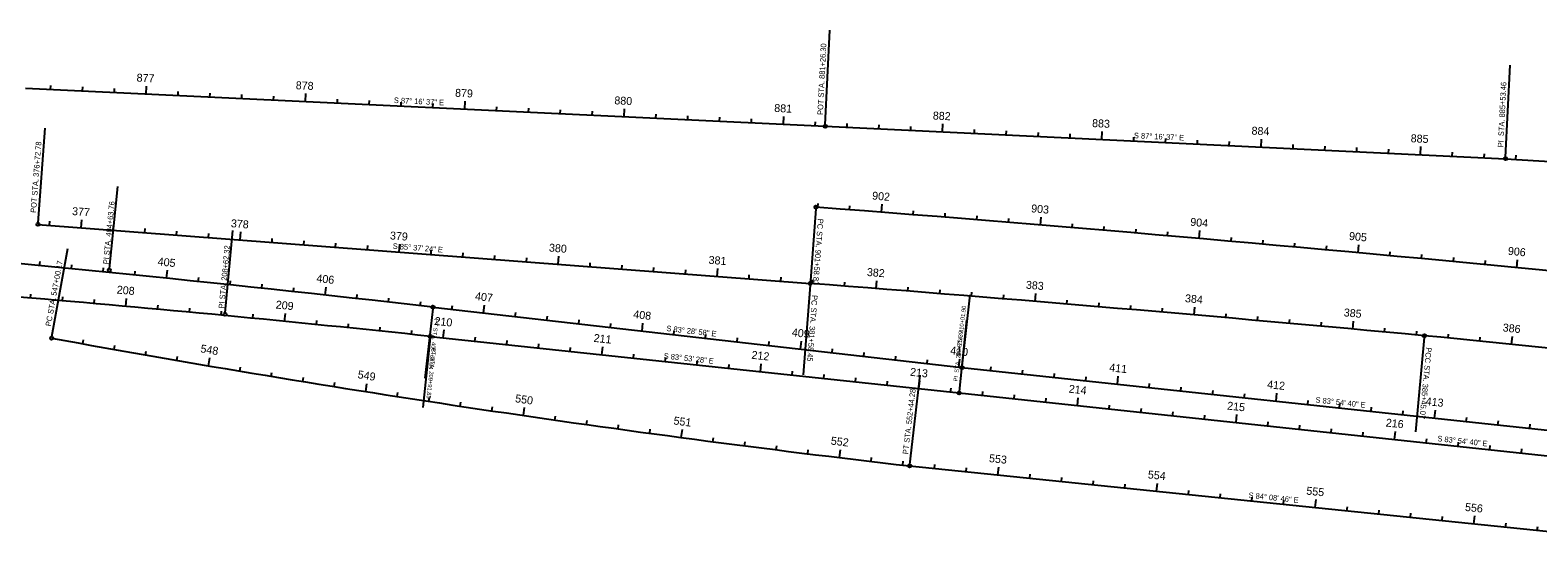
# Model space of a CAD drawing. Extents: x 919452 to 931278, y 583254 to 665650.
# Drawn here: x 926069 to 927014, y 636633 to 636954 of the extents above; entities that cross this region are included whole.
import ezdxf

# ---------------------------------------------------------------- set-up
doc = ezdxf.new("R2010")
doc.units = 0
for name, color, linetype in [('CLConst_dp', 7, 'Continuous'), ('CurveDataLabel_dp', 7, 'Continuous'), ('StationTicL_dp', 7, 'Continuous'), ('StationTicS_dp', 7, 'Continuous'), ('TextBLStation', 7, 'Continuous'), ('TextLabel', 7, 'Continuous')]:
    doc.layers.add(name, color=color, linetype=linetype)

msp = doc.modelspace()

# ---------------------------------------------------------------- linework, layer by layer
at = {"layer": 'CLConst_dp'}
for p, q in [((926065.6, 636917.34), (926567.14, 636893.49)), ((926567.14, 636893.49), (926993.81, 636873.2)), ((926993.81, 636873.2), (927628.09, 636834.88)), ((926073.42, 636831.99), (926557.68, 636794.93)), ((926321.15, 636780.1), (926652.85, 636742.2)), ((926319.5, 636761.79), (926651.16, 636726.29)), ((926652.85, 636742.2), (927135.36, 636690.73)), ((926651.16, 636726.29), (927289.95, 636658.15)), ((926620.06, 636680.55), (927084.21, 636632.96))]:
    msp.add_line(p, q, dxfattribs=at)
for centre, radius, start, end in [((924808.61, 613941.45), 22968.31, 83.189634, 85.623449), ((924651.1, 622161.18), 14714, 83.482815, 85.073773), ((924808.61, 613941.45), 22920.31, 84.656985, 85.623449), ((925098.46, 625352.94), 11474, 83.891103, 85.184769), ((926386.43, 630812.14), 5976, 78.354474, 84.656985), ((927580.46, 644977.15), 8352, 259.664221, 263.396902)]:
    msp.add_arc(centre, radius, start, end, dxfattribs=at)
at = {"layer": 'CurveDataLabel_dp'}
for p, q in [((926567.19, 636894.49), (926570.01, 636953.77)), ((926993.86, 636874.19), (926996.6, 636931.84)), ((926073.5, 636832.98), (926078.03, 636892.23)), ((926118.27, 636804.28), (926123.43, 636855.78)), ((926561.27, 636841.79), (926556.97, 636785.6)), ((926190.8, 636776.57), (926195.73, 636828.16)), ((926082.15, 636761.66), (926092.24, 636816.93)), ((926557.6, 636793.93), (926553.31, 636737.77)), ((926652.97, 636743.2), (926658.08, 636787.93)), ((926321.04, 636779.1), (926316.06, 636735.55)), ((926651.26, 636727.29), (926656.05, 636772.06)), ((926319.4, 636760.79), (926314.72, 636717.12)), ((926942.81, 636761.18), (926937.27, 636701.97)), ((926620.17, 636681.54), (926626.64, 636737.4))]:
    msp.add_line(p, q, dxfattribs=at)
for centre in [(926567.14, 636893.49), (926993.81, 636873.2), (926561.34, 636842.79), (926073.42, 636831.99), (926118.17, 636803.28), (926557.68, 636794.93), (926321.15, 636780.1), (926190.7, 636775.57), (926081.97, 636760.67), (926319.5, 636761.79), (926942.91, 636762.17), (926652.85, 636742.2), (926651.16, 636726.29), (926620.06, 636680.55)]:
    msp.add_circle(centre, 1, dxfattribs=at)
at = {"layer": 'StationTicL_dp'}
for p, q in [((926141.32, 636913.74), (926141.56, 636918.74)), ((926241.2, 636908.99), (926241.44, 636913.98)), ((926341.09, 636904.24), (926341.33, 636909.23)), ((926440.98, 636899.49), (926441.22, 636904.48)), ((926540.87, 636894.74), (926541.1, 636899.73)), ((926640.75, 636889.99), (926640.99, 636894.98)), ((926740.64, 636885.24), (926740.88, 636890.23)), ((926840.53, 636880.49), (926840.76, 636885.48)), ((926940.41, 636875.73), (926940.65, 636880.73)), ((926602.39, 636839.61), (926602.78, 636844.59)), ((926702.07, 636831.58), (926702.48, 636836.56)), ((926100.56, 636829.91), (926100.95, 636834.9)), ((926200.27, 636822.28), (926200.65, 636827.26)), ((926801.71, 636823.12), (926802.14, 636828.1)), ((926299.98, 636814.65), (926300.36, 636819.63)), ((926901.31, 636814.22), (926901.77, 636819.2)), ((926399.69, 636807.02), (926400.07, 636812)), ((927000.88, 636804.9), (927001.35, 636809.87)), ((926154.1, 636798.21), (926154.61, 636803.19)), ((926499.4, 636799.39), (926499.78, 636804.37)), ((926253.54, 636787.66), (926254.08, 636792.63)), ((926599.1, 636791.72), (926599.49, 636796.7)), ((926128.58, 636780.61), (926129.03, 636785.59)), ((926352.91, 636776.47), (926353.48, 636781.44)), ((926698.78, 636783.69), (926699.19, 636788.67)), ((926798.42, 636775.22), (926798.86, 636780.2)), ((926228.14, 636771.2), (926228.63, 636776.17)), ((926898.03, 636766.33), (926898.48, 636771.3)), ((926327.61, 636760.92), (926328.14, 636765.89)), ((926452.26, 636765.12), (926452.83, 636770.09)), ((926997.57, 636756.81), (926998.08, 636761.78)), ((926427.04, 636750.28), (926427.57, 636755.25)), ((926551.62, 636753.77), (926552.19, 636758.74)), ((926180.29, 636743.35), (926181.13, 636748.28)), ((926526.47, 636739.64), (926527.01, 636744.61)), ((926650.97, 636742.42), (926651.54, 636747.39)), ((926625.91, 636729), (926626.44, 636733.97)), ((926750.41, 636731.8), (926750.94, 636736.77)), ((926278.97, 636727.18), (926279.75, 636732.11)), ((926725.34, 636718.38), (926725.87, 636723.35)), ((926849.84, 636721.19), (926850.37, 636726.16)), ((926377.84, 636712.18), (926378.56, 636717.13)), ((926949.28, 636710.58), (926949.81, 636715.55)), ((926824.78, 636707.77), (926825.31, 636712.74)), ((926476.88, 636698.38), (926477.54, 636703.33)), ((926924.21, 636697.17), (926924.74, 636702.14)), ((926576.08, 636685.76), (926576.68, 636690.72)), ((926675.49, 636674.87), (926676, 636679.84)), ((926774.96, 636664.67), (926775.47, 636669.64)), ((926874.44, 636654.47), (926874.95, 636659.44)), ((926973.92, 636644.27), (926974.43, 636649.24))]:
    msp.add_line(p, q, dxfattribs=at)
at = {"layer": 'StationTicS_dp'}
for p, q in [((926081.39, 636916.59), (926081.5, 636919.09)), ((926101.36, 636915.64), (926101.48, 636918.14)), ((926121.34, 636914.69), (926121.46, 636917.19)), ((926161.29, 636912.79), (926161.41, 636915.29)), ((926181.27, 636911.84), (926181.39, 636914.34)), ((926201.25, 636910.89), (926201.37, 636913.39)), ((926221.23, 636909.94), (926221.35, 636912.44)), ((926261.18, 636908.04), (926261.3, 636910.54)), ((926281.16, 636907.09), (926281.28, 636909.59)), ((926301.14, 636906.14), (926301.26, 636908.64)), ((926321.11, 636905.19), (926321.23, 636907.69)), ((926361.07, 636903.29), (926361.19, 636905.79)), ((926381.05, 636902.34), (926381.17, 636904.84)), ((926401.02, 636901.39), (926401.14, 636903.89)), ((926421, 636900.44), (926421.12, 636902.94)), ((926460.96, 636898.54), (926461.07, 636901.04)), ((926480.93, 636897.59), (926481.05, 636900.09)), ((926500.91, 636896.64), (926501.03, 636899.14)), ((926520.89, 636895.69), (926521.01, 636898.19)), ((926560.84, 636893.79), (926560.96, 636896.29)), ((926580.82, 636892.84), (926580.94, 636895.33)), ((926600.8, 636891.89), (926600.92, 636894.38)), ((926620.78, 636890.94), (926620.89, 636893.43)), ((926660.73, 636889.04), (926660.85, 636891.53)), ((926680.71, 636888.09), (926680.83, 636890.58)), ((926700.69, 636887.14), (926700.8, 636889.63)), ((926720.66, 636886.19), (926720.78, 636888.68)), ((926760.62, 636884.29), (926760.74, 636886.78)), ((926780.59, 636883.34), (926780.71, 636885.83)), ((926800.57, 636882.39), (926800.69, 636884.88)), ((926820.55, 636881.44), (926820.67, 636883.93)), ((926860.5, 636879.54), (926860.62, 636882.03)), ((926880.48, 636878.59), (926880.6, 636881.08)), ((926900.46, 636877.64), (926900.58, 636880.13)), ((926920.44, 636876.69), (926920.56, 636879.18)), ((926960.39, 636874.78), (926960.51, 636877.28)), ((926980.37, 636873.83), (926980.49, 636876.33)), ((927000.34, 636872.8), (927000.49, 636875.3)), ((926562.51, 636842.7), (926562.7, 636845.19)), ((926582.45, 636841.16), (926582.64, 636843.65)), ((926622.33, 636838.04), (926622.53, 636840.53)), ((926642.27, 636836.45), (926642.46, 636838.94)), ((926662.2, 636834.84), (926662.4, 636837.33)), ((926080.62, 636831.44), (926080.81, 636833.93)), ((926120.51, 636828.38), (926120.7, 636830.88)), ((926140.45, 636826.86), (926140.64, 636829.35)), ((926160.39, 636825.33), (926160.58, 636827.82)), ((926682.13, 636833.22), (926682.34, 636835.71)), ((926722, 636829.92), (926722.21, 636832.41)), ((926741.93, 636828.25), (926742.14, 636830.74)), ((926761.86, 636826.56), (926762.07, 636829.05)), ((926781.78, 636824.85), (926782, 636827.34)), ((926180.33, 636823.81), (926180.52, 636826.3)), ((926220.21, 636820.75), (926220.41, 636823.25)), ((926240.16, 636819.23), (926240.35, 636821.72)), ((926260.1, 636817.7), (926260.29, 636820.19)), ((926280.04, 636816.17), (926280.23, 636818.67)), ((926821.63, 636821.38), (926821.85, 636823.87)), ((926841.55, 636819.61), (926841.78, 636822.1)), ((926861.48, 636817.83), (926861.7, 636820.32)), ((926881.39, 636816.04), (926881.62, 636818.53)), ((926074.49, 636806.17), (926074.74, 636808.66)), ((926319.92, 636813.12), (926320.11, 636815.61)), ((926339.86, 636811.6), (926340.06, 636814.09)), ((926359.81, 636810.07), (926360, 636812.56)), ((926379.75, 636808.54), (926379.94, 636811.04)), ((926419.63, 636805.49), (926419.82, 636807.98)), ((926921.23, 636812.39), (926921.46, 636814.88)), ((926941.14, 636810.55), (926941.37, 636813.03)), ((926961.06, 636808.68), (926961.29, 636811.17)), ((926980.97, 636806.8), (926981.2, 636809.29)), ((926094.4, 636804.22), (926094.64, 636806.71)), ((926114.3, 636802.25), (926114.55, 636804.73)), ((926134.2, 636800.24), (926134.45, 636802.73)), ((926173.99, 636796.16), (926174.25, 636798.64)), ((926439.57, 636803.96), (926439.76, 636806.46)), ((926459.52, 636802.44), (926459.71, 636804.93)), ((926479.46, 636800.91), (926479.65, 636803.4)), ((926519.34, 636797.86), (926519.53, 636800.35)), ((926539.28, 636796.33), (926539.47, 636798.83)), ((926193.88, 636794.07), (926194.14, 636796.56)), ((926213.77, 636791.96), (926214.04, 636794.45)), ((926233.66, 636789.83), (926233.92, 636792.31)), ((926559.22, 636794.81), (926559.41, 636797.3)), ((926579.16, 636793.27), (926579.36, 636795.76)), ((926619.04, 636790.15), (926619.24, 636792.64)), ((926638.98, 636788.56), (926639.18, 636791.05)), ((926658.91, 636786.95), (926659.12, 636789.44)), ((926068.81, 636785.84), (926069.02, 636788.33)), ((926088.74, 636784.13), (926088.96, 636786.62)), ((926108.66, 636782.39), (926108.88, 636784.88)), ((926148.5, 636778.8), (926148.73, 636781.29)), ((926273.42, 636785.47), (926273.69, 636787.96)), ((926293.29, 636783.25), (926293.57, 636785.74)), ((926313.17, 636781.01), (926313.45, 636783.49)), ((926333.04, 636778.74), (926333.32, 636781.22)), ((926678.85, 636785.33), (926679.05, 636787.82)), ((926718.71, 636782.03), (926718.92, 636784.52)), ((926738.64, 636780.35), (926738.85, 636782.85)), ((926758.57, 636778.66), (926758.78, 636781.15)), ((926168.42, 636776.95), (926168.65, 636779.44)), ((926188.33, 636775.07), (926188.57, 636777.55)), ((926208.24, 636773.15), (926208.48, 636775.64)), ((926248.04, 636769.21), (926248.29, 636771.7)), ((926372.78, 636774.2), (926373.06, 636776.68)), ((926392.65, 636771.93), (926392.94, 636774.41)), ((926412.52, 636769.66), (926412.81, 636772.14)), ((926778.5, 636776.95), (926778.71, 636779.44)), ((926818.35, 636773.48), (926818.56, 636775.97)), ((926838.27, 636771.72), (926838.49, 636774.21)), ((926858.19, 636769.94), (926858.41, 636772.43)), ((926878.11, 636768.14), (926878.33, 636770.63)), ((926267.94, 636767.19), (926268.19, 636769.68)), ((926287.83, 636765.13), (926288.09, 636767.62)), ((926307.72, 636763.04), (926307.99, 636765.53)), ((926347.5, 636758.79), (926347.76, 636761.28)), ((926432.39, 636767.39), (926432.68, 636769.87)), ((926472.13, 636762.85), (926472.42, 636765.33)), ((926492.01, 636760.58), (926492.29, 636763.06)), ((926511.88, 636758.31), (926512.16, 636760.79)), ((926917.94, 636764.49), (926918.17, 636766.98)), ((926937.86, 636762.64), (926938.09, 636765.13)), ((926957.77, 636760.76), (926958.01, 636763.25)), ((926977.67, 636758.82), (926977.92, 636761.31)), ((926101.49, 636757.14), (926101.93, 636759.6)), ((926121.18, 636753.62), (926121.61, 636756.08)), ((926140.87, 636750.15), (926141.3, 636752.61)), ((926367.38, 636756.66), (926367.65, 636759.15)), ((926387.27, 636754.54), (926387.54, 636757.02)), ((926407.16, 636752.41), (926407.42, 636754.89)), ((926531.75, 636756.04), (926532.03, 636758.52)), ((926571.49, 636751.5), (926571.77, 636753.98)), ((926591.36, 636749.23), (926591.64, 636751.71)), ((926160.58, 636746.73), (926161, 636749.19)), ((926200.01, 636740.02), (926200.42, 636742.49)), ((926446.93, 636748.15), (926447.2, 636750.64)), ((926466.82, 636746.02), (926467.08, 636748.51)), ((926486.7, 636743.89), (926486.97, 636746.38)), ((926506.59, 636741.77), (926506.85, 636744.25)), ((926611.23, 636746.96), (926611.51, 636749.44)), ((926631.1, 636744.69), (926631.38, 636747.17)), ((926670.86, 636740.28), (926671.12, 636742.77)), ((926219.74, 636736.74), (926220.15, 636739.2)), ((926239.48, 636733.5), (926239.88, 636735.97)), ((926259.22, 636730.32), (926259.62, 636732.78)), ((926546.36, 636737.51), (926546.63, 636739.99)), ((926566.25, 636735.38), (926566.51, 636737.87)), ((926586.13, 636733.25), (926586.4, 636735.74)), ((926606.02, 636731.12), (926606.29, 636733.61)), ((926690.74, 636738.16), (926691.01, 636740.65)), ((926710.63, 636736.04), (926710.9, 636738.53)), ((926730.52, 636733.92), (926730.78, 636736.4)), ((926298.73, 636724.08), (926299.12, 636726.55)), ((926318.5, 636721.04), (926318.88, 636723.51)), ((926645.79, 636726.87), (926646.06, 636729.35)), ((926665.68, 636724.74), (926665.95, 636727.23)), ((926685.57, 636722.62), (926685.83, 636725.11)), ((926705.45, 636720.5), (926705.72, 636722.99)), ((926770.29, 636729.68), (926770.56, 636732.16)), ((926790.18, 636727.55), (926790.45, 636730.04)), ((926810.07, 636725.43), (926810.33, 636727.92)), ((926829.95, 636723.31), (926830.22, 636725.8)), ((926338.27, 636718.04), (926338.64, 636720.51)), ((926358.05, 636715.09), (926358.42, 636717.56)), ((926745.23, 636716.26), (926745.49, 636718.74)), ((926765.12, 636714.14), (926765.38, 636716.62)), ((926785, 636712.02), (926785.27, 636714.5)), ((926869.73, 636719.07), (926869.99, 636721.55)), ((926889.62, 636716.95), (926889.88, 636719.43)), ((926909.5, 636714.83), (926909.77, 636717.31)), ((926929.39, 636712.7), (926929.66, 636715.19)), ((926397.64, 636709.33), (926397.99, 636711.8)), ((926417.44, 636706.52), (926417.79, 636709)), ((926437.25, 636703.76), (926437.59, 636706.23)), ((926804.89, 636709.89), (926805.16, 636712.38)), ((926844.66, 636705.65), (926844.93, 636708.14)), ((926864.55, 636703.53), (926864.82, 636706.02)), ((926969.16, 636708.46), (926969.43, 636710.95)), ((926989.05, 636706.34), (926989.32, 636708.83)), ((927008.94, 636704.22), (927009.2, 636706.7)), ((926457.06, 636701.04), (926457.4, 636703.52)), ((926496.71, 636695.76), (926497.04, 636698.24)), ((926516.55, 636693.19), (926516.86, 636695.67)), ((926884.44, 636701.41), (926884.7, 636703.89)), ((926904.33, 636699.29), (926904.59, 636701.77)), ((926944.1, 636695.04), (926944.37, 636697.53)), ((926963.99, 636692.92), (926964.25, 636695.41)), ((926536.39, 636690.66), (926536.7, 636693.14)), ((926556.23, 636688.19), (926556.54, 636690.67)), ((926595.94, 636683.38), (926596.24, 636685.86)), ((926983.88, 636690.8), (926984.14, 636693.29)), ((927003.76, 636688.68), (927004.03, 636691.17)), ((926615.8, 636681.04), (926616.09, 636683.53)), ((926635.69, 636678.95), (926635.95, 636681.43)), ((926655.59, 636676.91), (926655.84, 636679.39)), ((926695.38, 636672.83), (926695.64, 636675.31)), ((926715.28, 636670.79), (926715.53, 636673.27)), ((926735.17, 636668.75), (926735.43, 636671.23)), ((926755.07, 636666.71), (926755.32, 636669.19)), ((926794.86, 636662.63), (926795.11, 636665.12)), ((926814.76, 636660.59), (926815.01, 636663.08)), ((926834.65, 636658.55), (926834.91, 636661.04)), ((926854.55, 636656.51), (926854.8, 636659)), ((926894.34, 636652.43), (926894.59, 636654.92)), ((926914.23, 636650.39), (926914.49, 636652.88)), ((926934.13, 636648.35), (926934.38, 636650.84)), ((926954.03, 636646.31), (926954.28, 636648.8)), ((926993.82, 636642.23), (926994.07, 636644.72)), ((927013.71, 636640.19), (927013.97, 636642.68))]:
    msp.add_line(p, q, dxfattribs=at)

# ---------------------------------------------------------------- texts
at = {"layer": 'CurveDataLabel_dp'}
for s, height, rotation, p in [('POT STA. 881+26.30', 3.5, 87.27698, (926565.72, 636900.56)), ('PI  STA. 885+53.46', 3.5, 87.27698, (926992.4, 636880.27)), ('POT STA. 376+72.78', 3.5, 85.62345, (926072.21, 636839.1)), ('PI STA. 404+63.76', 3.5, 84.27829, (926117.65, 636806.85)), ('PC STA. 901+58.83', 3.5, 265.62345, (926562.55, 636835.67)), ('PI STA. 208+62.32', 3.5, 84.53794, (926190.16, 636779.14)), ('PC STA. 547+00.17', 3.5, 79.66422, (926081.51, 636767.87)), ('PC STA. 381+58.45', 3.5, 265.62345, (926558.89, 636787.81)), ('PI  STA. 410+01.90', 2.625, 83.48281, (926651.91, 636749.36)), ('PT STA. 406+68.04', 2.625, 263.48281, (926322.1, 636772.94)), ('PI  STA. 213+25.39', 2.625, 83.8911, (926650.16, 636733.44)), ('PT STA. 209+91.85', 2.625, 263.8911, (926320.5, 636754.64)), ('PCC STA. 385+45.07', 3.5, 264.65698, (926944, 636755.04)), ('PT STA. 552+44.28', 3.5, 83.3969, (926619.13, 636687.7))]:
    msp.add_text(s, height=height, rotation=rotation, dxfattribs=at).set_placement(p)
at = {"layer": 'TextBLStation'}
for s, rotation, p in [('877', 357.27698, (926135.21, 636921.54)), ('878', 357.27698, (926235, 636916.79)), ('879', 357.27698, (926334.92, 636912.04)), ('880', 357.27698, (926434.82, 636907.29)), ('881', 357.27698, (926535.09, 636902.52)), ('882', 357.27698, (926634.53, 636897.79)), ('883', 357.27698, (926734.41, 636893.04)), ('884', 357.27698, (926834.4, 636888.29)), ('885', 357.27698, (926934.21, 636883.54)), ('902', 355.52075, (926596.41, 636847.6)), ('377', 355.62345, (926094.68, 636837.88)), ('903', 355.27129, (926696.12, 636839.6)), ('378', 355.62345, (926194.29, 636830.26)), ('379', 355.62345, (926294.04, 636822.62)), ('904', 355.02184, (926795.9, 636831.15)), ('905', 354.77238, (926895.46, 636822.29)), ('380', 355.62345, (926393.76, 636814.99)), ('906', 354.52292, (926995.09, 636812.99)), ('405', 354.13714, (926148.33, 636806.35)), ('381', 355.62345, (926493.85, 636807.33)), ('406', 353.74775, (926247.86, 636795.83)), ('382', 355.51959, (926593.12, 636799.71)), ('208', 354.8491, (926122.71, 636788.67)), ('407', 353.48281, (926347.33, 636784.65)), ('383', 355.26961, (926692.83, 636791.71)), ('209', 354.34975, (926222.38, 636779.3)), ('384', 355.01963, (926792.61, 636783.26)), ('210', 353.8911, (926321.92, 636769.07)), ('408', 353.48281, (926446.59, 636773.32)), ('385', 354.76965, (926892.17, 636774.39)), ('211', 353.8911, (926421.74, 636758.39)), ('409', 353.48281, (926545.98, 636761.96)), ('386', 354.13035, (926991.84, 636764.93)), ('548', 350.34907, (926175.07, 636751.85)), ('212', 353.8911, (926520.72, 636747.8)), ('410', 353.48281, (926645.34, 636750.61)), ('213', 353.8911, (926620.15, 636737.15)), ('411', 353.91108, (926745.1, 636739.91)), ('549', 351.03508, (926273.69, 636735.6)), ('412', 353.91108, (926844.09, 636729.35)), ('550', 351.72109, (926372.47, 636720.55)), ('214', 353.91108, (926719.69, 636726.53)), ('413', 353.91108, (926943.52, 636718.74)), ('215', 353.91108, (926819.04, 636715.93)), ('551', 352.40711, (926471.79, 636706.62)), ('216', 353.91108, (926918.51, 636705.32)), ('552', 353.09312, (926570.45, 636694)), ('553', 354.14623, (926669.7, 636683)), ('554', 354.14623, (926769.28, 636672.79)), ('555', 354.14623, (926868.68, 636662.6)), ('556', 354.14623, (926968.19, 636652.4))]:
    msp.add_text(s, height=5, rotation=rotation, dxfattribs=at).set_placement(p)
at = {"layer": 'TextLabel'}
for s, rotation, p in [('S 87%%d 16\' 37" E', 357.27698, (926296.55, 636908.11)), ('S 87%%d 16\' 37" E', 357.27698, (926760.66, 636886.04)), ('S 85%%d 37\' 24" E', 355.62345, (926295.82, 636816.72)), ('S 83%%d 28\' 58" E', 353.48281, (926467.41, 636765.15)), ('S 83%%d 53\' 28" E', 353.8911, (926465.71, 636747.9)), ('S 83%%d 54\' 40" E', 353.91108, (926874.48, 636720.32)), ('S 83%%d 54\' 40" E', 353.91108, (926950.93, 636696.08)), ('S 84%%d 08\' 46" E', 354.14623, (926832.49, 636660.53))]:
    msp.add_text(s, height=3.5, rotation=rotation, dxfattribs=at).set_placement(p)

doc.saveas('drawing.dxf')
